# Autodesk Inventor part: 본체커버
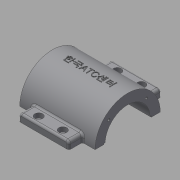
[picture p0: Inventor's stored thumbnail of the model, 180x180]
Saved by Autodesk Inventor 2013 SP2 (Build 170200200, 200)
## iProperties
Created: 2015-12
Part Number: 본체커버
Material: 일반
Document SubType Name: Modeling
Designer: mduedu
Density: 1 g/cm^3
Mass: 73.5601 g
Surface Area: 200.806 cm^2
Volume: 73.5601 cm^3
Author: mduedu
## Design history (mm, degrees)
sketch "스케치1"
  geometry: L1 (45, 40)-(-45, 40); L2 (-45, 40)-(-45, -40); L3 (-45, -40)-(45, -40); L4 (45, -40)-(45, 40); L5 (45, 40)-(-45, -40); L6 (-45, 40)-(45, -40); 1 further point
  constraints: 12 end point, 2 midpoint, 2 parallel, 1 horizontal, 1 perpendicular
  dimensions: "d0" = 90 distance of L2.end L3.end; "d2" = 80 distance of L1.end L2.end
extrude "돌출1" new body sketch "스케치1" distance "d3" = 10; taper "d4" = 0 deg
sketch "스케치2"
  geometry: L1 (0, 40)-(0, -40) reference; C1 r 32.5 at (80, 0); 1 further point
  constraints: 1 centre point
  dimensions: "d5" = 65 diameter of C1; "d6" = 80 distance from line of C1.centre L1
extrude "돌출2" join sketch "스케치2" stored distance "d7" = 75; taper "d8" = 0 deg
sketch "스케치3"
  geometry: L1 (-27.5, -20)-(27.5, -20); L2 (27.5, -20)-(27.5, 20); L3 (27.5, 20)-(-27.5, 20); L4 (-27.5, 20)-(-27.5, -20); L5 (-27.5, -20)-(27.5, 20); L6 (27.5, -20)-(-27.5, 20); 1 further point
  constraints: 12 end point, 2 midpoint, 2 parallel, 1 horizontal, 1 perpendicular
  dimensions: "d9" = 55 distance of L2.end L3.end; "d11" = 40 distance of L1.end L2.end
extrude "돌출3" new body sketch "스케치3" stored distance "d12" = 75; taper "d13" = 0 deg
fillet "모깎기1"
fillet "모깎기2"
feature "결합1"
  node "솔리드2"
fillet "모깎기3" dims "d14" = 10
sketch "스케치4"
  geometry: L1 (-37.5, 47.5)-(37.5, 47.5) reference; L2 (35, 10)-(45, 10) reference; L3 (32.5, 47.5)-(40, 10); L4 (37.5, 47.5)-(37.5, 112.5) reference; L5 (45, 10)-(45, 0) reference; 1 further point
  constraints: 2 end point, 1 midpoint, 1 point on line
  dimensions: "d15" = 5 distance from line of L3.start L4; "d16" = 5 distance from line of L3.end L5
sketch "스케치5"
  geometry: L1 (10, 40)-(10, 30) reference; L2 (10, 35)-(56.569, 22.522); L3 (0, 40)-(10, 40) reference; 2 further points
  constraints: 2 end point, 1 midpoint, 2 other
  dimensions: "d17" = 5 distance from line of L2.start L3; "d18" = 15 deg angle of L2 L3
feature "리브1" dims "d19" = 1, "d20" = 6, "d21" = 0, "d22" = 0, "d23" = 1, "d24" = 1
feature "리브2" dims "d25" = 1, "d26" = 6, "d27" = 0, "d28" = 0, "d29" = 1, "d30" = 1
fillet "모깎기4" dims "d31" = 2
fillet "모깎기5" dims "d32" = 2
fillet "모깎기6" dims "d33" = 2
sketch "스케치6"
  geometry: A1 r 10 centre (-35, 30) between (-35, 40) and (-45, 30) reference; A2 r 10 centre (35, 30) between (45, 30) and (35, 40) reference; A3 r 10 centre (35, -30) between (35, -40) and (45, -30) reference; A4 r 10 centre (-35, -30) between (-45, -30) and (-35, -40) reference; 5 further points
  constraints: 4 coincident
hole "구멍1" sketch "스케치6" at (-35, 30), (35, 30), (35, -30), (-35, -30) diameter "d34" = 7; stored, may be unused: countersink angle "d38" = 90 deg, drill point angle "d40" = 118 deg; dims "d35" = 6, "d36" = 12, "d37" = 3, "d39" = 8
fillet "모깎기7" dims "d41" = 2
hole "구멍2" diameter "d44" = 45; stored, may be unused: countersink angle "d48" = 90 deg, drill point angle "d50" = 118 deg; dims "d42" = 10, "d43" = 10, "d45" = 6, "d46" = 4, "d47" = 2, "d49" = 8
sketch "스케치7" dims "d52" = 26.5
  geometry: L1 (0, 0)-(32.5, 0); L2 (0, 0)-(22.981, 22.981); A1 r 32.5 centre (0, 0) between (32.5, 0) and (22.981, 22.981) reference; 3 further points
  constraints: 4 end point, 2 point on circle, 1 coincident, 1 horizontal, 1 point on line, 3 other
  dimensions: "d51" = 45 deg angle of L2 L1
hole "구멍3" sketch "스케치7" at (18.738, 18.738) diameter "d54" = 2.459; stored, may be unused: countersink angle "d58" = 90 deg, drill point angle "d60" = 118 deg; dims "d55" = 8, "d56" = 4, "d57" = 2, "d59" = 10
sketch "스케치8"
  geometry: L1 (72.5, 31.623)-(72.5, 46); L2 (72.5, 46)-(87.5, 46); L3 (87.5, 46)-(87.5, 31.623); A1 r 32.5 centre (80, 0) between (87.5, 31.623) and (72.5, 31.623) reference; 2 further points
  constraints: 6 end point, 2 point on circle, 1 midpoint, 1 parallel, 1 vertical, 1 vertical alignment
  dimensions: "d64" = 15 distance of L1.end L2.end; "d66" = 46 distance from line of L2 A1.centre
extrude "돌출4" join sketch "스케치8" stored distance "d67" = 50; taper "d68" = 0 deg
fillet "모깎기8" dims "d69" = 3
fillet "모깎기9" dims "d70" = 2
sketch "스케치13"
  geometry: L1 (-46, 80)-(106, 80); L2 (106, 80)-(106, -30); L3 (106, -30)-(-46, -30); L4 (-46, -30)-(-46, 80); L5 (0, 0)-(60, 0) reference; L6 (76, 75.5)-(76, 84.5) reference; C1 r 32.5 at (30, 80) reference; 1 further point
  constraints: 8 end point, 2 parallel, 1 coincident, 1 horizontal, 1 midpoint, 1 perpendicular
  dimensions: "d99" = 30 distance between parallel lines of L3 L5; "d100" = 30 distance between parallel lines of L2 L6
extrude "돌출8" cut sketch "스케치13" stored distance "d97" = 10; taper "d98" = 0 deg
node "작업 평면2"
sketch "스케치14"
  geometry: 2 further points
  constraints: 1 coincident, 1 other
feature "엠보싱1" sketch "스케치14" dims "d28" = 0, "d102" = 0.5, "d103" = 0
feature "립1" dims "d104" = 1, "d105" = 1.1, "d106" = 0, "d107" = 0, "d108" = 3 deg, "d109" = 0
sketch "스케치15"
  geometry: L1 (-3, -1.039)-(-3, -10.834) reference; L2 (47, -10.834)-(47, -1.039) reference; L3 (-3, -5.936)-(47, -5.936); L4 (-15.5, 65.666)-(-15.5, 0.666) reference; L5 (59.5, 0.666)-(59.5, 65.666) reference; L6 (-15.5, 33.166)-(59.5, 33.166); 5 further points
  constraints: 4 end point, 4 midpoint, 2 point on line, 2 symmetric about line
  dimensions: "d110" = 13 distance from line of point (10, -5.936) L1; "d111" = 13 distance from line of point (34, -5.936) L2
sketch "스케치16"
  geometry: 4 further points
hole "구멍5" sketch "스케치16" at (34, -5.936), (10, 72.269), (34, 72.269), (10, -5.936) diameter "d112" = 4.5; stored, may be unused: countersink angle "d116" = 90 deg, drill point angle "d118" = 0 deg; dims "d113" = 6, "d114" = 8, "d115" = 4.6, "d117" = 8
node "솔리드1"
mirror "대칭1"
mirror "대칭2"
pattern_circular "원형 패턴1" dims angle "d62" = 360 deg
mirror "대칭3"
mirror "대칭4"
